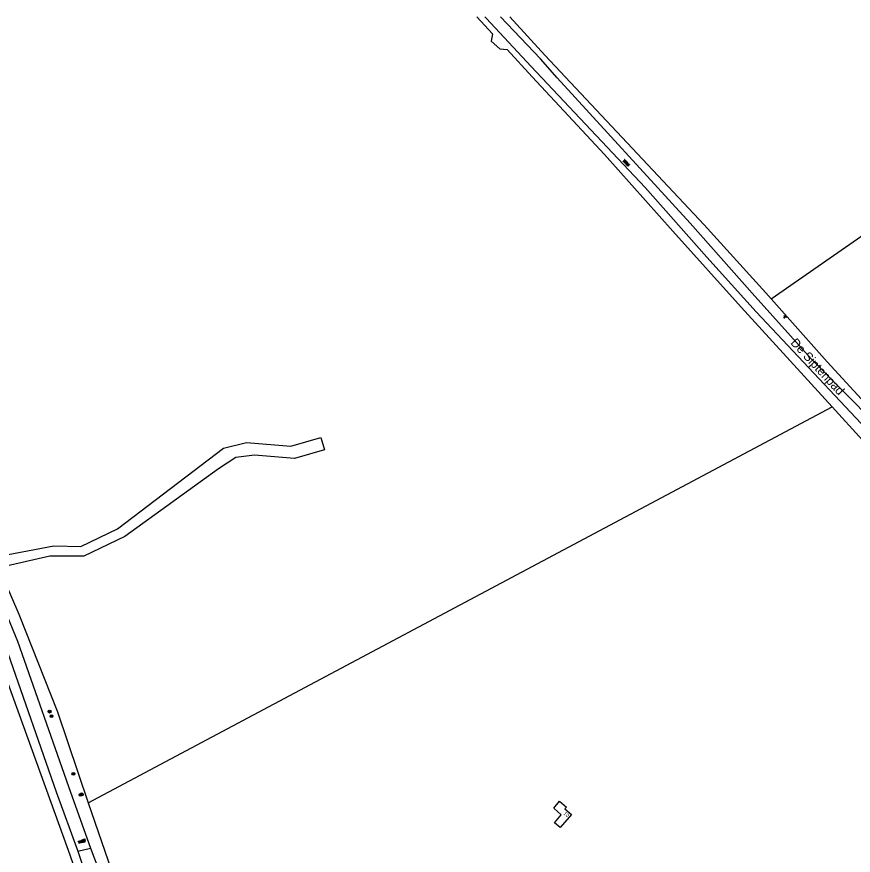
# Model space of a CAD drawing. Extents: x 126000 to 131009, y 393000 to 395500.
# Drawn here: x 128529.7 to 128765.6, y 395263.5 to 395500 of the extents above; entities that cross this region are included whole.
import ezdxf

# ---------------------------------------------------------------- set-up
doc = ezdxf.new("R2010")
doc.units = 0
for name, color, linetype in [('gg-afsc-draadraster', 7, 'Continuous'), ('gg-anno-huisnummerreeks BGT', 7, 'Continuous'), ('gg-anno-openbare ruimte label', 7, 'Continuous'), ('gg-bbg-hoofdgebouw', 7, 'Continuous'), ('gg-knt-onverhard', 7, 'Continuous'), ('gg-knt-verharding nz', 7, 'Continuous'), ('gt-grn-vlakafsluiter', 7, 'Continuous'), ('gt-symb-boom', 7, 'Continuous'), ('gt-symb-groenvak', 7, 'Continuous'), ('gt-symb-overige verharding', 7, 'Continuous')]:
    doc.layers.add(name, color=color, linetype=linetype)

# ---------------------------------------------------------------- blocks, each defined once
blk = doc.blocks.new('gt0-OVH')
at = {"layer": 'gt-symb-overige verharding'}
for points in [[(-0.97, 0.3), (-0.97, 0.31), (-0.96, 0.32), (-0.97, 0.33), (-0.97, 0.34), (-0.98, 0.35), (-0.99, 0.35), (-1, 0.36), (-1.01, 0.35), (-1.02, 0.35), (-1.03, 0.34), (-1.03, 0.33), (-1.04, 0.32), (-1.03, 0.31), (-1.03, 0.3), (-1.02, 0.29), (-1.01, 0.29), (-1, 0.28), (-0.99, 0.29), (-0.98, 0.29)], [(-0.87, 0.11), (-0.87, 0.12), (-0.86, 0.13), (-0.87, 0.14), (-0.87, 0.15), (-0.88, 0.16), (-0.89, 0.16), (-0.9, 0.16), (-0.91, 0.16), (-0.92, 0.16), (-0.93, 0.15), (-0.93, 0.14), (-0.94, 0.13), (-0.93, 0.12), (-0.93, 0.11), (-0.92, 0.1), (-0.91, 0.09), (-0.9, 0.09), (-0.89, 0.09), (-0.88, 0.1)], [(-0.77, 0.3), (-0.77, 0.31), (-0.76, 0.32), (-0.77, 0.33), (-0.77, 0.34), (-0.78, 0.35), (-0.79, 0.35), (-0.8, 0.36), (-0.81, 0.35), (-0.82, 0.35), (-0.83, 0.34), (-0.83, 0.33), (-0.84, 0.32), (-0.83, 0.31), (-0.83, 0.3), (-0.82, 0.29), (-0.81, 0.29), (-0.8, 0.28), (-0.79, 0.29), (-0.78, 0.29)], [(-0.67, 0.11), (-0.67, 0.12), (-0.66, 0.13), (-0.67, 0.14), (-0.67, 0.15), (-0.68, 0.16), (-0.69, 0.16), (-0.7, 0.16), (-0.71, 0.16), (-0.72, 0.16), (-0.73, 0.15), (-0.73, 0.14), (-0.74, 0.13), (-0.73, 0.12), (-0.73, 0.11), (-0.72, 0.1), (-0.71, 0.09), (-0.7, 0.09), (-0.69, 0.09), (-0.68, 0.1)], [(-0.57, 0.3), (-0.57, 0.31), (-0.56, 0.32), (-0.57, 0.33), (-0.57, 0.34), (-0.58, 0.35), (-0.59, 0.35), (-0.6, 0.36), (-0.61, 0.35), (-0.62, 0.35), (-0.63, 0.34), (-0.63, 0.33), (-0.64, 0.32), (-0.63, 0.31), (-0.63, 0.3), (-0.62, 0.29), (-0.61, 0.29), (-0.6, 0.28), (-0.59, 0.29), (-0.58, 0.29)], [(-0.47, 0.11), (-0.47, 0.12), (-0.46, 0.13), (-0.47, 0.14), (-0.47, 0.15), (-0.48, 0.16), (-0.49, 0.16), (-0.5, 0.16), (-0.51, 0.16), (-0.52, 0.16), (-0.53, 0.15), (-0.53, 0.14), (-0.54, 0.13), (-0.53, 0.12), (-0.53, 0.11), (-0.52, 0.1), (-0.51, 0.09), (-0.5, 0.09), (-0.49, 0.09), (-0.48, 0.1)], [(-0.37, 0.3), (-0.37, 0.31), (-0.36, 0.32), (-0.37, 0.33), (-0.37, 0.34), (-0.38, 0.35), (-0.39, 0.35), (-0.4, 0.36), (-0.41, 0.35), (-0.42, 0.35), (-0.43, 0.34), (-0.43, 0.33), (-0.44, 0.32), (-0.43, 0.31), (-0.43, 0.3), (-0.42, 0.29), (-0.41, 0.29), (-0.4, 0.28), (-0.39, 0.29), (-0.38, 0.29)], [(-0.27, 0.11), (-0.27, 0.12), (-0.26, 0.13), (-0.27, 0.14), (-0.27, 0.15), (-0.28, 0.16), (-0.29, 0.16), (-0.3, 0.16), (-0.31, 0.16), (-0.32, 0.16), (-0.33, 0.15), (-0.33, 0.14), (-0.34, 0.13), (-0.33, 0.12), (-0.33, 0.11), (-0.32, 0.1), (-0.31, 0.09), (-0.3, 0.09), (-0.29, 0.09), (-0.28, 0.1)], [(-0.17, 0.3), (-0.17, 0.31), (-0.16, 0.32), (-0.17, 0.33), (-0.17, 0.34), (-0.18, 0.35), (-0.19, 0.35), (-0.2, 0.36), (-0.21, 0.35), (-0.22, 0.35), (-0.23, 0.34), (-0.23, 0.33), (-0.24, 0.32), (-0.23, 0.31), (-0.23, 0.3), (-0.22, 0.29), (-0.21, 0.29), (-0.2, 0.28), (-0.19, 0.29), (-0.18, 0.29)], [(-0.07, 0.11), (-0.07, 0.12), (-0.06, 0.13), (-0.07, 0.14), (-0.07, 0.15), (-0.08, 0.16), (-0.09, 0.16), (-0.1, 0.16), (-0.11, 0.16), (-0.12, 0.16), (-0.13, 0.15), (-0.13, 0.14), (-0.14, 0.13), (-0.13, 0.12), (-0.13, 0.11), (-0.12, 0.1), (-0.11, 0.09), (-0.1, 0.09), (-0.09, 0.09), (-0.08, 0.1)], [(0.03, 0.3), (0.03, 0.31), (0.04, 0.32), (0.03, 0.33), (0.03, 0.34), (0.02, 0.35), (0.01, 0.35), (0, 0.36), (-0.01, 0.35), (-0.02, 0.35), (-0.03, 0.34), (-0.03, 0.33), (-0.04, 0.32), (-0.03, 0.31), (-0.03, 0.3), (-0.02, 0.29), (-0.01, 0.29), (0, 0.28), (0.01, 0.29), (0.02, 0.29)], [(0.13, 0.11), (0.13, 0.12), (0.14, 0.13), (0.13, 0.14), (0.13, 0.15), (0.12, 0.16), (0.11, 0.16), (0.1, 0.16), (0.09, 0.16), (0.08, 0.16), (0.07, 0.15), (0.07, 0.14), (0.06, 0.13), (0.07, 0.12), (0.07, 0.11), (0.08, 0.1), (0.09, 0.09), (0.1, 0.09), (0.11, 0.09), (0.12, 0.1)], [(0.23, 0.3), (0.23, 0.31), (0.24, 0.32), (0.23, 0.33), (0.23, 0.34), (0.22, 0.35), (0.21, 0.35), (0.2, 0.36), (0.19, 0.35), (0.18, 0.35), (0.17, 0.34), (0.17, 0.33), (0.16, 0.32), (0.17, 0.31), (0.17, 0.3), (0.18, 0.29), (0.19, 0.29), (0.2, 0.28), (0.21, 0.29), (0.22, 0.29)], [(0.33, 0.11), (0.33, 0.12), (0.34, 0.13), (0.33, 0.14), (0.33, 0.15), (0.32, 0.16), (0.31, 0.16), (0.3, 0.16), (0.29, 0.16), (0.28, 0.16), (0.27, 0.15), (0.27, 0.14), (0.26, 0.13), (0.27, 0.12), (0.27, 0.11), (0.28, 0.1), (0.29, 0.09), (0.3, 0.09), (0.31, 0.09), (0.32, 0.1)], [(0.43, 0.3), (0.43, 0.31), (0.44, 0.32), (0.43, 0.33), (0.43, 0.34), (0.42, 0.35), (0.41, 0.35), (0.4, 0.36), (0.39, 0.35), (0.38, 0.35), (0.37, 0.34), (0.37, 0.33), (0.36, 0.32), (0.37, 0.31), (0.37, 0.3), (0.38, 0.29), (0.39, 0.29), (0.4, 0.28), (0.41, 0.29), (0.42, 0.29)], [(0.53, 0.11), (0.53, 0.12), (0.54, 0.13), (0.53, 0.14), (0.53, 0.15), (0.52, 0.16), (0.51, 0.16), (0.5, 0.16), (0.49, 0.16), (0.48, 0.16), (0.47, 0.15), (0.47, 0.14), (0.46, 0.13), (0.47, 0.12), (0.47, 0.11), (0.48, 0.1), (0.49, 0.09), (0.5, 0.09), (0.51, 0.09), (0.52, 0.1)], [(0.63, 0.3), (0.63, 0.31), (0.64, 0.32), (0.63, 0.33), (0.63, 0.34), (0.62, 0.35), (0.61, 0.35), (0.6, 0.36), (0.59, 0.35), (0.58, 0.35), (0.57, 0.34), (0.57, 0.33), (0.56, 0.32), (0.57, 0.31), (0.57, 0.3), (0.58, 0.29), (0.59, 0.29), (0.6, 0.28), (0.61, 0.29), (0.62, 0.29)], [(0.73, 0.11), (0.73, 0.12), (0.74, 0.13), (0.73, 0.14), (0.73, 0.15), (0.72, 0.16), (0.71, 0.16), (0.7, 0.16), (0.69, 0.16), (0.68, 0.16), (0.67, 0.15), (0.67, 0.14), (0.66, 0.13), (0.67, 0.12), (0.67, 0.11), (0.68, 0.1), (0.69, 0.09), (0.7, 0.09), (0.71, 0.09), (0.72, 0.1)], [(0.83, 0.3), (0.83, 0.31), (0.84, 0.32), (0.83, 0.33), (0.83, 0.34), (0.82, 0.35), (0.81, 0.35), (0.8, 0.36), (0.79, 0.35), (0.78, 0.35), (0.77, 0.34), (0.77, 0.33), (0.76, 0.32), (0.77, 0.31), (0.77, 0.3), (0.78, 0.29), (0.79, 0.29), (0.8, 0.28), (0.81, 0.29), (0.82, 0.29)], [(0.93, 0.11), (0.93, 0.12), (0.94, 0.13), (0.93, 0.14), (0.93, 0.15), (0.92, 0.16), (0.91, 0.16), (0.9, 0.16), (0.89, 0.16), (0.88, 0.16), (0.87, 0.15), (0.87, 0.14), (0.86, 0.13), (0.87, 0.12), (0.87, 0.11), (0.88, 0.1), (0.89, 0.09), (0.9, 0.09), (0.91, 0.09), (0.92, 0.1)], [(1.03, 0.3), (1.03, 0.31), (1.04, 0.32), (1.03, 0.33), (1.03, 0.34), (1.02, 0.35), (1.01, 0.35), (1, 0.36), (0.99, 0.35), (0.98, 0.35), (0.97, 0.34), (0.97, 0.33), (0.96, 0.32), (0.97, 0.31), (0.97, 0.3), (0.98, 0.29), (0.99, 0.29), (1, 0.28), (1.01, 0.29), (1.02, 0.29)], [(-0.97, -0.14), (-0.97, -0.13), (-0.96, -0.12), (-0.97, -0.11), (-0.97, -0.1), (-0.98, -0.09), (-0.99, -0.09), (-1, -0.08), (-1.01, -0.09), (-1.02, -0.09), (-1.03, -0.1), (-1.03, -0.11), (-1.04, -0.12), (-1.03, -0.13), (-1.03, -0.14), (-1.02, -0.15), (-1.01, -0.15), (-1, -0.16), (-0.99, -0.15), (-0.98, -0.15)], [(-0.87, -0.33), (-0.87, -0.32), (-0.86, -0.31), (-0.87, -0.3), (-0.87, -0.29), (-0.88, -0.28), (-0.89, -0.28), (-0.9, -0.28), (-0.91, -0.28), (-0.92, -0.28), (-0.93, -0.29), (-0.93, -0.3), (-0.94, -0.31), (-0.93, -0.32), (-0.93, -0.33), (-0.92, -0.34), (-0.91, -0.35), (-0.9, -0.35), (-0.89, -0.35), (-0.88, -0.34)], [(-0.77, -0.14), (-0.77, -0.13), (-0.76, -0.12), (-0.77, -0.11), (-0.77, -0.1), (-0.78, -0.09), (-0.79, -0.09), (-0.8, -0.08), (-0.81, -0.09), (-0.82, -0.09), (-0.83, -0.1), (-0.83, -0.11), (-0.84, -0.12), (-0.83, -0.13), (-0.83, -0.14), (-0.82, -0.15), (-0.81, -0.15), (-0.8, -0.16), (-0.79, -0.15), (-0.78, -0.15)], [(-0.67, -0.33), (-0.67, -0.32), (-0.66, -0.31), (-0.67, -0.3), (-0.67, -0.29), (-0.68, -0.28), (-0.69, -0.28), (-0.7, -0.28), (-0.71, -0.28), (-0.72, -0.28), (-0.73, -0.29), (-0.73, -0.3), (-0.74, -0.31), (-0.73, -0.32), (-0.73, -0.33), (-0.72, -0.34), (-0.71, -0.35), (-0.7, -0.35), (-0.69, -0.35), (-0.68, -0.34)], [(-0.57, -0.14), (-0.57, -0.13), (-0.56, -0.12), (-0.57, -0.11), (-0.57, -0.1), (-0.58, -0.09), (-0.59, -0.09), (-0.6, -0.08), (-0.61, -0.09), (-0.62, -0.09), (-0.63, -0.1), (-0.63, -0.11), (-0.64, -0.12), (-0.63, -0.13), (-0.63, -0.14), (-0.62, -0.15), (-0.61, -0.15), (-0.6, -0.16), (-0.59, -0.15), (-0.58, -0.15)], [(-0.47, -0.33), (-0.47, -0.32), (-0.46, -0.31), (-0.47, -0.3), (-0.47, -0.29), (-0.48, -0.28), (-0.49, -0.28), (-0.5, -0.28), (-0.51, -0.28), (-0.52, -0.28), (-0.53, -0.29), (-0.53, -0.3), (-0.54, -0.31), (-0.53, -0.32), (-0.53, -0.33), (-0.52, -0.34), (-0.51, -0.35), (-0.5, -0.35), (-0.49, -0.35), (-0.48, -0.34)], [(-0.37, -0.14), (-0.37, -0.13), (-0.36, -0.12), (-0.37, -0.11), (-0.37, -0.1), (-0.38, -0.09), (-0.39, -0.09), (-0.4, -0.08), (-0.41, -0.09), (-0.42, -0.09), (-0.43, -0.1), (-0.43, -0.11), (-0.44, -0.12), (-0.43, -0.13), (-0.43, -0.14), (-0.42, -0.15), (-0.41, -0.15), (-0.4, -0.16), (-0.39, -0.15), (-0.38, -0.15)], [(-0.27, -0.33), (-0.27, -0.32), (-0.26, -0.31), (-0.27, -0.3), (-0.27, -0.29), (-0.28, -0.28), (-0.29, -0.28), (-0.3, -0.28), (-0.31, -0.28), (-0.32, -0.28), (-0.33, -0.29), (-0.33, -0.3), (-0.34, -0.31), (-0.33, -0.32), (-0.33, -0.33), (-0.32, -0.34), (-0.31, -0.35), (-0.3, -0.35), (-0.29, -0.35), (-0.28, -0.34)], [(-0.17, -0.14), (-0.17, -0.13), (-0.16, -0.12), (-0.17, -0.11), (-0.17, -0.1), (-0.18, -0.09), (-0.19, -0.09), (-0.2, -0.08), (-0.21, -0.09), (-0.22, -0.09), (-0.23, -0.1), (-0.23, -0.11), (-0.24, -0.12), (-0.23, -0.13), (-0.23, -0.14), (-0.22, -0.15), (-0.21, -0.15), (-0.2, -0.16), (-0.19, -0.15), (-0.18, -0.15)], [(-0.07, -0.33), (-0.07, -0.32), (-0.06, -0.31), (-0.07, -0.3), (-0.07, -0.29), (-0.08, -0.28), (-0.09, -0.28), (-0.1, -0.28), (-0.11, -0.28), (-0.12, -0.28), (-0.13, -0.29), (-0.13, -0.3), (-0.14, -0.31), (-0.13, -0.32), (-0.13, -0.33), (-0.12, -0.34), (-0.11, -0.35), (-0.1, -0.35), (-0.09, -0.35), (-0.08, -0.34)], [(0.03, -0.14), (0.03, -0.13), (0.04, -0.12), (0.03, -0.11), (0.03, -0.1), (0.02, -0.09), (0.01, -0.09), (0, -0.08), (-0.01, -0.09), (-0.02, -0.09), (-0.03, -0.1), (-0.03, -0.11), (-0.04, -0.12), (-0.03, -0.13), (-0.03, -0.14), (-0.02, -0.15), (-0.01, -0.15), (0, -0.16), (0.01, -0.15), (0.02, -0.15)], [(0.13, -0.33), (0.13, -0.32), (0.14, -0.31), (0.13, -0.3), (0.13, -0.29), (0.12, -0.28), (0.11, -0.28), (0.1, -0.28), (0.09, -0.28), (0.08, -0.28), (0.07, -0.29), (0.07, -0.3), (0.06, -0.31), (0.07, -0.32), (0.07, -0.33), (0.08, -0.34), (0.09, -0.35), (0.1, -0.35), (0.11, -0.35), (0.12, -0.34)], [(0.23, -0.14), (0.23, -0.13), (0.24, -0.12), (0.23, -0.11), (0.23, -0.1), (0.22, -0.09), (0.21, -0.09), (0.2, -0.08), (0.19, -0.09), (0.18, -0.09), (0.17, -0.1), (0.17, -0.11), (0.16, -0.12), (0.17, -0.13), (0.17, -0.14), (0.18, -0.15), (0.19, -0.15), (0.2, -0.16), (0.21, -0.15), (0.22, -0.15)], [(0.33, -0.33), (0.33, -0.32), (0.34, -0.31), (0.33, -0.3), (0.33, -0.29), (0.32, -0.28), (0.31, -0.28), (0.3, -0.28), (0.29, -0.28), (0.28, -0.28), (0.27, -0.29), (0.27, -0.3), (0.26, -0.31), (0.27, -0.32), (0.27, -0.33), (0.28, -0.34), (0.29, -0.35), (0.3, -0.35), (0.31, -0.35), (0.32, -0.34)], [(0.43, -0.14), (0.43, -0.13), (0.44, -0.12), (0.43, -0.11), (0.43, -0.1), (0.42, -0.09), (0.41, -0.09), (0.4, -0.08), (0.39, -0.09), (0.38, -0.09), (0.37, -0.1), (0.37, -0.11), (0.36, -0.12), (0.37, -0.13), (0.37, -0.14), (0.38, -0.15), (0.39, -0.15), (0.4, -0.16), (0.41, -0.15), (0.42, -0.15)], [(0.53, -0.33), (0.53, -0.32), (0.54, -0.31), (0.53, -0.3), (0.53, -0.29), (0.52, -0.28), (0.51, -0.28), (0.5, -0.28), (0.49, -0.28), (0.48, -0.28), (0.47, -0.29), (0.47, -0.3), (0.46, -0.31), (0.47, -0.32), (0.47, -0.33), (0.48, -0.34), (0.49, -0.35), (0.5, -0.35), (0.51, -0.35), (0.52, -0.34)], [(0.63, -0.14), (0.63, -0.13), (0.64, -0.12), (0.63, -0.11), (0.63, -0.1), (0.62, -0.09), (0.61, -0.09), (0.6, -0.08), (0.59, -0.09), (0.58, -0.09), (0.57, -0.1), (0.57, -0.11), (0.56, -0.12), (0.57, -0.13), (0.57, -0.14), (0.58, -0.15), (0.59, -0.15), (0.6, -0.16), (0.61, -0.15), (0.62, -0.15)], [(0.73, -0.33), (0.73, -0.32), (0.74, -0.31), (0.73, -0.3), (0.73, -0.29), (0.72, -0.28), (0.71, -0.28), (0.7, -0.28), (0.69, -0.28), (0.68, -0.28), (0.67, -0.29), (0.67, -0.3), (0.66, -0.31), (0.67, -0.32), (0.67, -0.33), (0.68, -0.34), (0.69, -0.35), (0.7, -0.35), (0.71, -0.35), (0.72, -0.34)], [(0.83, -0.14), (0.83, -0.13), (0.84, -0.12), (0.83, -0.11), (0.83, -0.1), (0.82, -0.09), (0.81, -0.09), (0.8, -0.08), (0.79, -0.09), (0.78, -0.09), (0.77, -0.1), (0.77, -0.11), (0.76, -0.12), (0.77, -0.13), (0.77, -0.14), (0.78, -0.15), (0.79, -0.15), (0.8, -0.16), (0.81, -0.15), (0.82, -0.15)], [(0.93, -0.33), (0.93, -0.32), (0.94, -0.31), (0.93, -0.3), (0.93, -0.29), (0.92, -0.28), (0.91, -0.28), (0.9, -0.28), (0.89, -0.28), (0.88, -0.28), (0.87, -0.29), (0.87, -0.3), (0.86, -0.31), (0.87, -0.32), (0.87, -0.33), (0.88, -0.34), (0.89, -0.35), (0.9, -0.35), (0.91, -0.35), (0.92, -0.34)], [(1.03, -0.14), (1.03, -0.13), (1.04, -0.12), (1.03, -0.11), (1.03, -0.1), (1.02, -0.09), (1.01, -0.09), (1, -0.08), (0.99, -0.09), (0.98, -0.09), (0.97, -0.1), (0.97, -0.11), (0.96, -0.12), (0.97, -0.13), (0.97, -0.14), (0.98, -0.15), (0.99, -0.15), (1, -0.16), (1.01, -0.15), (1.02, -0.15)]]:
    blk.add_lwpolyline(points, close=True, dxfattribs=at)
blk = doc.blocks.new('gt0-GRVAK')
at = {"layer": 'gt-symb-groenvak'}
for p, q in [((-0.11, 0.19), (-0.23, 0.24)), ((-0.18, 0.15), (0.09, 0.15)), ((-0.09, 0.21), (-0.16, 0.32)), ((-0.05, 0.21), (-0.05, 0.39)), ((0, 0.21), (0.06, 0.32)), ((0.01, 0.19), (0.13, 0.24)), ((0.26, -0.05), (0.2, 0.06)), ((0.3, -0.05), (0.3, 0.13)), ((0.35, -0.05), (0.41, 0.06)), ((-0.25, -0.23), (-0.36, -0.18)), ((-0.32, -0.26), (-0.05, -0.26)), ((-0.23, -0.21), (-0.29, -0.1)), ((-0.18, -0.2), (-0.18, -0.02)), ((-0.14, -0.21), (-0.07, -0.1)), ((-0.12, -0.23), (0, -0.18)), ((0.24, -0.07), (0.12, -0.02)), ((0.17, -0.11), (0.44, -0.11)), ((0.37, -0.07), (0.49, -0.02))]:
    blk.add_line(p, q, dxfattribs=at)
blk = doc.blocks.new('gt0-BOOM')
at = {"layer": 'gt-symb-boom'}
for radius in [0.4, 0.2]:
    blk.add_circle((0, 0), radius, dxfattribs=at)

msp = doc.modelspace()

# ---------------------------------------------------------------- linework, layer by layer
at = {"layer": 'gg-afsc-draadraster'}
for points in [[(128659.44, 395500), (128663.91, 395495.23), (128663.51, 395493.14), (128665.92, 395490.91), (128668.01, 395490.75), (128675.05, 395483.05), (128695.42, 395461.14), (128714.76, 395439.53), (128733.97, 395418.08), (128759.66, 395389.94)], [(128668.73, 395500), (128678.6, 395489.2), (128698.96, 395467.5), (128723.6, 395441.36), (128740.92, 395422.15), (128742.43, 395420.45)], [(128742.43, 395420.45), (128758.27, 395402.68), (128767.91, 395392.11)], [(128759.66, 395389.94), (128785.36, 395361.8), (128795.05, 395352.39), (128804.34, 395343.14), (128803.51, 395341.73), (128805.89, 395339.2), (128807.6, 395340.48), (128823.75, 395322.33), (128842.55, 395301.48), (128846.18, 395296.69)], [(128524.54, 395344.59), (128530.28, 395331.47), (128541.19, 395303.97), (128549.83, 395278.32)], [(128559.04, 395222.78), (128544.25, 395264.86), (128523.46, 395322.14), (128472.55, 395311.21), (128381.66, 395292.13), (128359.9, 395287.75), (128357.81, 395287.3)], [(128549.83, 395278.32), (128556.4, 395259.25), (128569.31, 395225.77), (128572.84, 395215.49)]]:
    msp.add_lwpolyline(points, dxfattribs=at)
at = {"layer": 'gg-bbg-hoofdgebouw'}
msp.add_lwpolyline([(128681.14, 395276.77), (128682.8, 395278.72), (128684.74, 395277.08), (128684.31, 395276.57), (128686.15, 395275.02), (128682.92, 395271.32), (128681.34, 395272.66), (128683.28, 395274.95), (128681.14, 395276.77)], dxfattribs=at)
at = {"layer": 'gg-knt-onverhard'}
for points in [[(128661.73, 395500), (128662.06, 395499.65), (128674.77, 395485.93), (128706.92, 395451.86), (128724.35, 395432.18), (128738.2, 395416.81), (128778.22, 395374.3), (128796.21, 395355.3), (128807.98, 395343.1), (128820.63, 395329.57), (128837.64, 395310.41), (128851.12, 395294.37), (128863.71, 395276.11), (128878.29, 395255.18), (128888.47, 395240.64), (128901.2, 395221.99), (128917.43, 395198.13), (128932.46, 395176.55), (128941.18, 395164.7), (128966.76, 395127.64), (128990.77, 395093.54), (129016.71, 395054.94), (129035.18, 395028.62), (129045.2, 395014.67)], [(128771.93, 395385.16), (128753.71, 395403.55), (128737.11, 395422.02), (128719.61, 395441.82), (128682.07, 395482.8), (128677.42, 395488.11), (128666.13, 395500)], [(128523.18, 395347.62), (128540.11, 395350.76), (128547.76, 395350.55), (128558.05, 395355.55), (128588.03, 395378.31), (128594.45, 395379.94), (128606.99, 395378.92), (128615.46, 395381.37), (128616.48, 395377.85), (128608.04, 395375.41), (128596.7, 395376.39), (128591.5, 395375.68), (128586.61, 395372.51), (128560.2, 395353.43), (128548.58, 395347.82), (128539, 395347.82), (128524.54, 395344.59)], [(128521.94, 395342.87), (128529.92, 395323.86), (128544.27, 395282.93), (128550.49, 395265.46)], [(128527.19, 395320.46), (128540.76, 395281.39), (128546.86, 395264.64)], [(128550.49, 395265.46), (128565.42, 395226.11), (128569.99, 395214.52), (128572.84, 395215.49)], [(128546.86, 395264.64), (128560.51, 395223.8), (128559.04, 395222.78)]]:
    msp.add_lwpolyline(points, dxfattribs=at)
at = {"layer": 'gg-knt-verharding nz'}
msp.add_line((128546.86, 395264.64), (128550.49, 395265.46), dxfattribs=at)
at = {"layer": 'gt-grn-vlakafsluiter'}
for p, q in [((128742.43, 395420.45), (128839.53, 395487.92)), ((128549.83, 395278.32), (128759.66, 395389.94))]:
    msp.add_line(p, q, dxfattribs=at)

# ---------------------------------------------------------------- block references
at = {"layer": 'gt-symb-boom'}
for p in [(128538.94, 395304.02), (128539.45, 395302.74), (128545.65, 395286.49), (128547.64, 395280.58), (128548, 395280.67)]:
    msp.add_blockref('gt0-BOOM', p, dxfattribs=at)
at = {"layer": 'gt-symb-groenvak'}
msp.add_blockref('gt0-GRVAK', (128746.33, 395415.39), dxfattribs=at)
at = {"layer": 'gt-symb-overige verharding'}
for p, rotation in [((128701.58, 395458.79), -48.40451830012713), ((128548.04, 395267.42), 17.220699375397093)]:
    msp.add_blockref('gt0-OVH', p, dxfattribs=dict(at, rotation=rotation))

# ---------------------------------------------------------------- texts
at = {"layer": 'gg-anno-huisnummerreeks BGT'}
msp.add_text('10', height=1, rotation=319.6, dxfattribs=at).set_placement((128683.8, 395275.16))
at = {"layer": 'gg-anno-openbare ruimte label'}
msp.add_text('De Siptenpad', height=2.5, rotation=312.8, dxfattribs=at).set_placement((128747.78, 395407.92))

doc.saveas('drawing.dxf')
